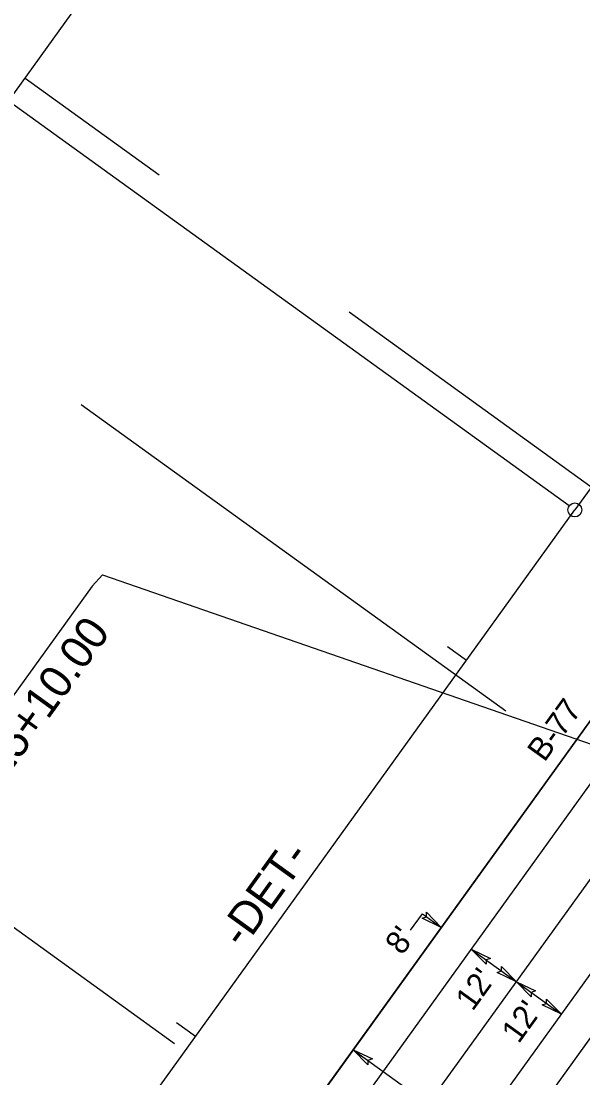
# Model space of a CAD drawing. Extents: x 2189281 to 2191267, y 386656 to 389012.
# Drawn here: x 2190273 to 2190394.2, y 387931.7 to 388159.5 of the extents above; entities that cross this region are included whole.
import ezdxf

# ---------------------------------------------------------------- set-up
doc = ezdxf.new("R2010")
doc.units = 0
for name, color, linetype in [('Prop Dimension', 7, 'Continuous'), ('Prop Dimension Text', 7, 'Continuous'), ('Prop DSN Text', 7, 'Continuous'), ('Prop EOT', 7, 'Continuous'), ('Prop Guardrail Anchor Unit CELL', 7, 'Continuous'), ('Prop Horizontal Alignment', 7, 'Continuous'), ('Prop Horizontal Alignment Station Label', 7, 'Continuous'), ('Prop Horizontal Alignment Tick Small', 7, 'Continuous'), ('Prop Paved Shoulder', 7, 'Continuous'), ('Prop Roadway Bridge', 7, 'Continuous'), ('Prop Terminator CELL', 7, 'Continuous'), ('Scratch_Level_5', 7, 'Continuous')]:
    doc.layers.add(name, color=color, linetype=linetype)

msp = doc.modelspace()

# ---------------------------------------------------------------- linework, layer by layer
at = {"layer": 'Prop Dimension'}
for p, q in [((2190357.01, 387963.5), (2190359.55, 387967.04)), ((2190359.55, 387967.04), (2190363.53, 387964.17)), ((2190370.12, 387959.42), (2190389.58, 387945.38)), ((2190344.62, 387937.74), (2190377.06, 387914.35))]:
    msp.add_line(p, q, dxfattribs=at)
at = {"layer": 'Prop DSN Text'}
msp.add_line((2190288.26, 388037.68), (2190240.06, 387970.84), dxfattribs=at)
msp.add_lwpolyline([(2190288.26, 388037.68), (2190290.51, 388040.13), (2190412.62, 387997.84)], dxfattribs=at)
at = {"layer": 'Prop EOT'}
msp.add_line((2190192.31, 387712.87), (2190484.78, 388118.41), dxfattribs=at)
msp.add_lwpolyline([(2190181.76, 387658.83), (2190211.78, 387698.83), (2190504.24, 388104.37), (2190532.84, 388145.39)], dxfattribs=at)
at = {"layer": 'Prop Horizontal Alignment'}
for p, q in [((2189529.37, 386773.11), (2190699.23, 388395.27)), ((2190236.81, 387838.31), (2190392.46, 388054.13))]:
    msp.add_line(p, q, dxfattribs=at)
msp.add_arc((2192257.95, 386708.79), 2300, 135.25499, 144.20184, dxfattribs=at)
at = {"layer": 'Prop Horizontal Alignment Station Label'}
msp.add_line((2190391.24, 388055.01), (2190169.41, 388214.99), dxfattribs=at)
msp.add_circle((2190392.46, 388054.13), 1.5, dxfattribs=at)
at = {"layer": 'Prop Horizontal Alignment Tick Small'}
for p, q in [((2190369.06, 388021.68), (2190365, 388024.61)), ((2190310.56, 387940.57), (2190306.51, 387943.5))]:
    msp.add_line(p, q, dxfattribs=at)
at = {"layer": 'Prop Paved Shoulder'}
for p, q in [((2190411.02, 388029.82), (2190288.67, 387860.16)), ((2190443.46, 388006.42), (2190321.11, 387836.77))]:
    msp.add_line(p, q, dxfattribs=at)
at = {"layer": 'Prop Roadway Bridge'}
msp.add_lwpolyline([(2190302.81, 387879.77), (2190396.4, 388009.54), (2190428.84, 387986.14), (2190335.25, 387856.37)], close=True, dxfattribs=at)
at = {"layer": 'Prop Terminator CELL'}
for points in [[(2190360.43, 387967.36), (2190363.63, 387964.1), (2190359.49, 387966.1), (2190360.42, 387966.41)], [(2190373.31, 387956.16), (2190370.12, 387959.42), (2190374.25, 387957.42), (2190373.32, 387957.11)], [(2190373.31, 387956.16), (2190370.12, 387959.42), (2190374.25, 387957.42), (2190373.32, 387957.11)], [(2190376.65, 387955.66), (2190379.85, 387952.4), (2190375.71, 387954.4), (2190376.64, 387954.71)], [(2190383.04, 387949.14), (2190379.85, 387952.4), (2190383.99, 387950.4), (2190383.05, 387950.09)], [(2190386.38, 387948.64), (2190389.58, 387945.38), (2190385.44, 387947.38), (2190386.38, 387947.69)], [(2190386.38, 387948.64), (2190389.58, 387945.38), (2190385.44, 387947.38), (2190386.38, 387947.69)], [(2190347.82, 387934.48), (2190344.62, 387937.74), (2190348.76, 387935.75), (2190347.82, 387935.43)]]:
    msp.add_lwpolyline(points, close=True, dxfattribs=at)
at = {"layer": 'Scratch_Level_5'}
for p, q in [((2189367.15, 386890.09), (2190537.02, 388512.26)), ((2190273.8, 388147.27), (2190302.74, 388126.4)), ((2190343.76, 388096.82), (2190397.82, 388057.83)), ((2190285.91, 388076.89), (2190377.54, 388010.81)), ((2190186.06, 388025.61), (2190306.09, 387939.05))]:
    msp.add_line(p, q, dxfattribs=at)

# ---------------------------------------------------------------- texts
at = {"layer": 'Prop Dimension Text'}
for s, p in [("8' ", (2190355.21, 387957.91)), ("12'", (2190370.4, 387945.86)), ("12'", (2190380.33, 387938.86))]:
    msp.add_text(s, height=5, rotation=54.2018, dxfattribs=at).set_placement(p)
at = {"layer": 'Prop DSN Text'}
for s, p in [('-L- STA. 25+10.00', (2190247.51, 387965.47)), ('-DET-', (2190320.84, 387959.34))]:
    msp.add_text(s, height=7, rotation=54.2018, dxfattribs=at).set_placement(p)
at = {"layer": 'Prop Guardrail Anchor Unit CELL'}
msp.add_text('B-77', height=5, rotation=54.2018, dxfattribs=at).set_placement((2190385.91, 387999.57))

doc.saveas('drawing.dxf')
